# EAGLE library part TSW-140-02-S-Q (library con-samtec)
THROUGH-HOLE .025" SQ POST HEADER Source: Samtec TSW.pdf
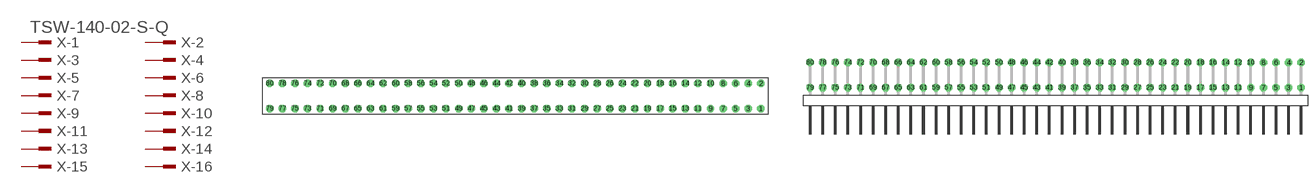
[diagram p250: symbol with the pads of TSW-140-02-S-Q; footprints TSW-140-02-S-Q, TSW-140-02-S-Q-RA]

Designator prefix X; gates -1=MPINV -2=MPIN -3=MPIN -4=MPIN -5=MPIN -6=MPIN -7=MPIN -8=MPIN -9=MPIN -10=MPIN -11=MPIN -12=MPIN -13=MPIN -14=MPIN -15=MPIN -16=MPIN -17=MPIN -18=MPIN -19=MPIN -20=MPIN -21=MPIN -22=MPIN -23=MPIN -24=MPIN -25=MPIN -26=MPIN -27=MPIN -28=MPIN -29=MPIN -30=MPIN -31=MPIN -32=MPIN -33=MPIN -34=MPIN -35=MPIN -36=MPIN -37=MPIN -38=MPIN -39=MPIN -40=MPIN -41=MPIN -42=MPIN -43=MPIN -44=MPIN -45=MPIN -46=MPIN -47=MPIN -48=MPIN -49=MPIN -50=MPIN -51=MPIN -52=MPIN -53=MPIN -54=MPIN -55=MPIN -56=MPIN -57=MPIN -58=MPIN -59=MPIN -60=MPIN -61=MPIN -62=MPIN -63=MPIN -64=MPIN -65=MPIN -66=MPIN -67=MPIN -68=MPIN -69=MPIN -70=MPIN -71=MPIN -72=MPIN -73=MPIN -74=MPIN -75=MPIN -76=MPIN -77=MPIN -78=MPIN -79=MPIN -80=MPIN

## TSW-140-02-S-Q (OC_FARNELL: unknown; OC_NEWARK: unknown)  [TSW-140-02-S-Q]
1  -1:1  pas
2  -2:1  pas
3  -3:1  pas
4  -4:1  pas
5  -5:1  pas
6  -6:1  pas
7  -7:1  pas
8  -8:1  pas
9  -9:1  pas
10  -10:1  pas
11  -11:1  pas
12  -12:1  pas
13  -13:1  pas
14  -14:1  pas
15  -15:1  pas
16  -16:1  pas
17  -17:1  pas
18  -18:1  pas
19  -19:1  pas
20  -20:1  pas
21  -21:1  pas
22  -22:1  pas
23  -23:1  pas
24  -24:1  pas
25  -25:1  pas
26  -26:1  pas
27  -27:1  pas
28  -28:1  pas
29  -29:1  pas
30  -30:1  pas
31  -31:1  pas
32  -32:1  pas
33  -33:1  pas
34  -34:1  pas
35  -35:1  pas
36  -36:1  pas
37  -37:1  pas
38  -38:1  pas
39  -39:1  pas
40  -40:1  pas
41  -41:1  pas
42  -42:1  pas
43  -43:1  pas
44  -44:1  pas
45  -45:1  pas
46  -46:1  pas
47  -47:1  pas
48  -48:1  pas
49  -49:1  pas
50  -50:1  pas
51  -51:1  pas
52  -52:1  pas
53  -53:1  pas
54  -54:1  pas
55  -55:1  pas
56  -56:1  pas
57  -57:1  pas
58  -58:1  pas
59  -59:1  pas
60  -60:1  pas
61  -61:1  pas
62  -62:1  pas
63  -63:1  pas
64  -64:1  pas
65  -65:1  pas
66  -66:1  pas
67  -67:1  pas
68  -68:1  pas
69  -69:1  pas
70  -70:1  pas
71  -71:1  pas
72  -72:1  pas
73  -73:1  pas
74  -74:1  pas
75  -75:1  pas
76  -76:1  pas
77  -77:1  pas
78  -78:1  pas
79  -79:1  pas
80  -80:1  pas

## TSW-140-02-S-Q-RA (OC_FARNELL: unknown; OC_NEWARK: unknown)  [TSW-140-02-S-Q-RA]
Pads as for TSW-140-02-S-Q

## Footprint TSW-140-02-S-Q (pad centres in mm)
THROUGH-HOLE .025" SQ POST HEADER Source: Samtec TSW.pdf
drill 1 pad 1.5 octagon: 1 49.53,-2.54; 2 49.53,2.54; 3 46.99,-2.54; 4 46.99,2.54; 5 44.45,-2.54; 6 44.45,2.54; 7 41.91,-2.54; 8 41.91,2.54; 9 39.37,-2.54; 10 39.37,2.54; 11 36.83,-2.54; 12 36.83,2.54; 13 34.29,-2.54; 14 34.29,2.54; 15 31.75,-2.54; 16 31.75,2.54; 17 29.21,-2.54; 18 29.21,2.54; 19 26.67,-2.54; 20 26.67,2.54; 21 24.13,-2.54; 22 24.13,2.54; 23 21.59,-2.54; 24 21.59,2.54; 25 19.05,-2.54; 26 19.05,2.54; 27 16.51,-2.54; 28 16.51,2.54; 29 13.97,-2.54; 30 13.97,2.54; 31 11.43,-2.54; 32 11.43,2.54; 33 8.89,-2.54; 34 8.89,2.54; 35 6.35,-2.54; 36 6.35,2.54; 37 3.81,-2.54; 38 3.81,2.54; 39 1.27,-2.54; 40 1.27,2.54; 41 -1.27,-2.54; 42 -1.27,2.54; 43 -3.81,-2.54; 44 -3.81,2.54; 45 -6.35,-2.54; 46 -6.35,2.54; 47 -8.89,-2.54; 48 -8.89,2.54; 49 -11.43,-2.54; 50 -11.43,2.54; 51 -13.97,-2.54; 52 -13.97,2.54; 53 -16.51,-2.54; 54 -16.51,2.54; 55 -19.05,-2.54; 56 -19.05,2.54; 57 -21.59,-2.54; 58 -21.59,2.54; 59 -24.13,-2.54; 60 -24.13,2.54; 61 -26.67,-2.54; 62 -26.67,2.54; 63 -29.21,-2.54; 64 -29.21,2.54; 65 -31.75,-2.54; 66 -31.75,2.54; 67 -34.29,-2.54; 68 -34.29,2.54; 69 -36.83,-2.54; 70 -36.83,2.54; 71 -39.37,-2.54; 72 -39.37,2.54; 73 -41.91,-2.54; 74 -41.91,2.54; 75 -44.45,-2.54; 76 -44.45,2.54; 77 -46.99,-2.54; 78 -46.99,2.54; 79 -49.53,-2.54; 80 -49.53,2.54

## Footprint TSW-140-02-S-Q-RA (pad centres in mm)
THROUGH-HOLE .025" SQ POST HEADER Source: Samtec TSW.pdf
drill 1 pad 1.5 octagon: 1 49.53,1.524; 2 49.53,6.604; 3 46.99,1.524; 4 46.99,6.604; 5 44.45,1.524; 6 44.45,6.604; 7 41.91,1.524; 8 41.91,6.604; 9 39.37,1.524; 10 39.37,6.604; 11 36.83,1.524; 12 36.83,6.604; 13 34.29,1.524; 14 34.29,6.604; 15 31.75,1.524; 16 31.75,6.604; 17 29.21,1.524; 18 29.21,6.604; 19 26.67,1.524; 20 26.67,6.604; 21 24.13,1.524; 22 24.13,6.604; 23 21.59,1.524; 24 21.59,6.604; 25 19.05,1.524; 26 19.05,6.604; 27 16.51,1.524; 28 16.51,6.604; 29 13.97,1.524; 30 13.97,6.604; 31 11.43,1.524; 32 11.43,6.604; 33 8.89,1.524; 34 8.89,6.604; 35 6.35,1.524; 36 6.35,6.604; 37 3.81,1.524; 38 3.81,6.604; 39 1.27,1.524; 40 1.27,6.604; 41 -1.27,1.524; 42 -1.27,6.604; 43 -3.81,1.524; 44 -3.81,6.604; 45 -6.35,1.524; 46 -6.35,6.604; 47 -8.89,1.524; 48 -8.89,6.604; 49 -11.43,1.524; 50 -11.43,6.604; 51 -13.97,1.524; 52 -13.97,6.604; 53 -16.51,1.524; 54 -16.51,6.604; 55 -19.05,1.524; 56 -19.05,6.604; 57 -21.59,1.524; 58 -21.59,6.604; 59 -24.13,1.524; 60 -24.13,6.604; 61 -26.67,1.524; 62 -26.67,6.604; 63 -29.21,1.524; 64 -29.21,6.604; 65 -31.75,1.524; 66 -31.75,6.604; 67 -34.29,1.524; 68 -34.29,6.604; 69 -36.83,1.524; 70 -36.83,6.604; 71 -39.37,1.524; 72 -39.37,6.604; 73 -41.91,1.524; 74 -41.91,6.604; 75 -44.45,1.524; 76 -44.45,6.604; 77 -46.99,1.524; 78 -46.99,6.604; 79 -49.53,1.524; 80 -49.53,6.604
